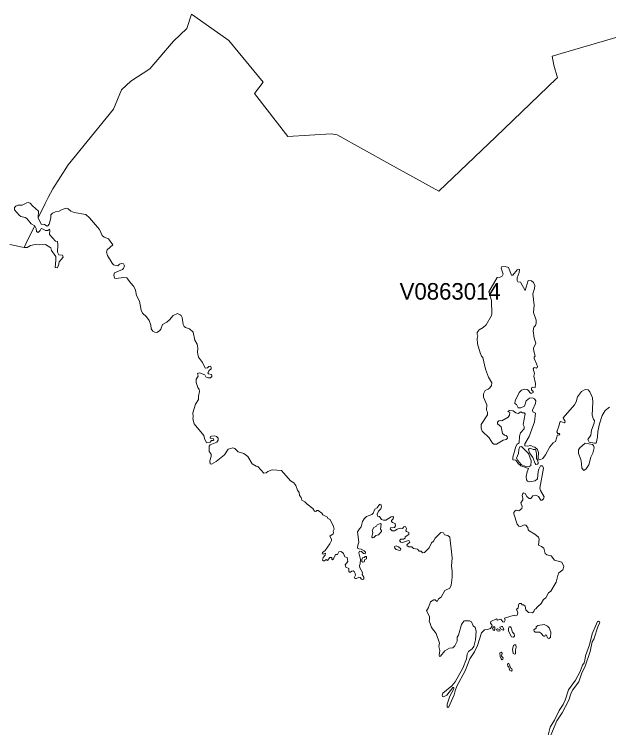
# Model space of a CAD drawing. Extents: x 369010 to 735936, y 6377141 to 6616555.
# Drawn here: x 477172 to 480757, y 6485532 to 6489836 of the extents above; entities that cross this region are included whole.
import ezdxf
from ezdxf.enums import TextEntityAlignment as Align

# ---------------------------------------------------------------- set-up
doc = ezdxf.new("R2010")
doc.units = 0
doc.header["$LTSCALE"] = 40
doc.layers.add('3', color=7, linetype='Continuous', lineweight=13)
doc.layers.add('4', color=7, linetype='Continuous')

msp = doc.modelspace()

# ---------------------------------------------------------------- linework, layer by layer
at = {"layer": '3'}
for points in [[(477144.89, 6488447.39), (477231.12, 6488427.7), (477252.3, 6488472.22), (477294.84, 6488559.6), (477273.16, 6488572.18), (477247.5, 6488604.29), (477237.74, 6488609.92), (477211.92, 6488614.72), (477200.67, 6488623.82), (477172.2, 6488655.1), (477172.86, 6488670.49), (477180.47, 6488678.27), (477193.71, 6488683.73), (477219.53, 6488683.07), (477247.5, 6488698.46), (477256.44, 6488700.45), (477268.36, 6488695.65), (477281.6, 6488679.59), (477318.5, 6488647.49), (477316.52, 6488608.43), (477357.73, 6488693.5), (477375.44, 6488730.57), (477404.9, 6488782.37), (477496.75, 6488927.68), (477770.83, 6489263.49), (477817.66, 6489379.51), (477873.94, 6489432.31), (477989.29, 6489506.95), (478131.96, 6489672.62), (478211.73, 6489749.41), (478240.03, 6489835.64), (478464.95, 6489676.42), (478672.99, 6489426.18), (478621.19, 6489358.49), (478821.94, 6489097.99), (479082.61, 6489114.37), (479118.2, 6489107.92), (479437.45, 6488931.32), (479732.05, 6488768.8), (480075.97, 6489096.33), (480441.07, 6489449.02), (480447.36, 6489452.5), (480425.51, 6489528.96), (480415.75, 6489582.91), (480423.86, 6489584.57), (480469.04, 6489599.3), (480862.61, 6489712.67)], [(480862.61, 6489712.67), (480469.04, 6489599.3), (480423.86, 6489584.57), (480415.75, 6489582.91), (480425.51, 6489528.96), (480447.36, 6489452.5), (480441.07, 6489449.02), (480075.97, 6489096.33), (479732.05, 6488768.8), (479437.45, 6488931.32), (479118.2, 6489107.92), (479082.61, 6489114.37), (478821.94, 6489097.99), (478621.19, 6489358.49), (478672.99, 6489426.18), (478464.95, 6489676.42), (478240.03, 6489835.64), (478211.73, 6489749.41), (478131.96, 6489672.62), (477989.29, 6489506.95), (477873.94, 6489432.31), (477817.66, 6489379.51), (477770.83, 6489263.49), (477496.75, 6488927.68), (477404.9, 6488782.37), (477375.44, 6488730.57), (477357.73, 6488693.5), (477316.52, 6488608.43), (477333.23, 6488568.71), (477354.09, 6488568.04), (477369.48, 6488558.28), (477374.28, 6488559.6), (477381.4, 6488569.37), (477393.15, 6488608.43), (477392.49, 6488625.14), (477402.91, 6488635.73), (477421.12, 6488644.67), (477442.63, 6488647.49), (477460.18, 6488657.25), (477484.51, 6488665.69), (477497.08, 6488662.88), (477513.14, 6488648.15), (477533.33, 6488639.21), (477603.01, 6488627.96), (477625.68, 6488608.59), (477685.59, 6488537.59), (477700.98, 6488500.52), (477714.22, 6488490.09), (477740.71, 6488480.33), (477766.52, 6488445.41), (477731.6, 6488414.79), (477728.79, 6488400.06), (477734.42, 6488381.36), (477761.56, 6488334.52), (477770.66, 6488324.09), (477797.14, 6488318.46), (477805.58, 6488327.57), (477818.16, 6488332.53), (477830.74, 6488330.38), (477836.86, 6488317.14), (477831.4, 6488301.75), (477823.62, 6488296.29), (477776.29, 6488275.27), (477772.15, 6488261.36), (477776.29, 6488243.99), (477785.39, 6488241.84), (477831.4, 6488248.12), (477851.59, 6488245.97), (477871.78, 6488216.02), (477891.98, 6488193.67), (477903.23, 6488170.67), (477908.03, 6488138.56), (477927.56, 6488105.79), (477936.66, 6488050.02), (477944.94, 6488033.3), (477968.77, 6488010.96), (477984.82, 6487988.61), (477995.25, 6487960.81), (477998.06, 6487937.8), (478007, 6487923.74), (478018.92, 6487917.45), (478032.16, 6487916.12), (478046.89, 6487925.23), (478055.16, 6487935.82), (478066.25, 6487964.78), (478091.24, 6487977.36), (478108.79, 6487991.92), (478130.47, 6488019.4), (478156.45, 6488029.66), (478171.68, 6488023.2), (478178.46, 6488018.57), (478184.59, 6488006.32), (478190.05, 6487964.78), (478195.84, 6487952.2), (478203.45, 6487945.75)], [(480048.99, 6488108.94), (480033.93, 6488160.41), (480083.91, 6488248.12), (480101.95, 6488249.28), (480114.86, 6488256.23), (480119.49, 6488267.98), (480107.25, 6488304.23), (480110.39, 6488311.51), (480132.9, 6488313.83), (480151.6, 6488308.04), (480170.64, 6488261.2), (480178.91, 6488261.53), (480203.9, 6488294.63), (480213.5, 6488298.44), (480218.8, 6488296.62), (480217.31, 6488277.09), (480204.4, 6488244.81), (480203.9, 6488228.76), (480208.54, 6488221.81), (480224.59, 6488220.32), (480252.39, 6488168.52), (480271.43, 6488228.76), (480291.95, 6488227.93), (480303.87, 6488217.34), (480310.32, 6488199.3), (480309.33, 6488181.76), (480299.89, 6488149.82), (480307.51, 6488080.8), (480302.71, 6488037.27), (480318.26, 6487989.94), (480318.76, 6487972.06), (480315.29, 6487958.33), (480305.36, 6487948.73), (480300.56, 6487926.72), (480308.17, 6487881.7), (480317.77, 6487851.58), (480303.87, 6487821.46), (480305.02, 6487804.24), (480314.13, 6487772.63), (480306.51, 6487766.51), (480307.34, 6487758.89), (480322.07, 6487727.28), (480326.37, 6487711.23), (480324.88, 6487703.95), (480318.6, 6487701.3), (480311.98, 6487705.44), (480304.36, 6487703.62), (480301.05, 6487697.16), (480309.82, 6487668.2), (480304.36, 6487652.48), (480315.78, 6487608.29), (480313.63, 6487584.62), (480299.07, 6487586.44), (480291.45, 6487582.3), (480291.12, 6487569.72), (480300.39, 6487559.46), (480300.39, 6487553.01), (480289.8, 6487546.88), (480281.03, 6487553.01), (480273.74, 6487566.74), (480264.97, 6487572.04), (480250.41, 6487573.53), (480231.38, 6487567.08), (480217.64, 6487554.17), (480191.65, 6487503.36), (480190.66, 6487487.3), (480201.25, 6487482.01), (480210.85, 6487461.81), (480227.24, 6487461.48), (480248.92, 6487471.41), (480258.02, 6487504.18), (480279.37, 6487520.24), (480298.07, 6487522.39), (480309.49, 6487515.27), (480316.78, 6487503.03), (480316.11, 6487487.8), (480296.25, 6487447.25), (480298.24, 6487437.82), (480315.12, 6487430.2), (480309, 6487376.75), (480276.06, 6487287.54), (480250.08, 6487243.68), (480250.41, 6487232.26), (480267.29, 6487229.94), (480286.32, 6487234.58), (480301.22, 6487226.14), (480311.81, 6487224.15), (480327.86, 6487209.26), (480332.83, 6487192.87), (480331.34, 6487158.28), (480333.99, 6487151.33), (480340.61, 6487146.86), (480359.31, 6487155.96), (480376.19, 6487176.98), (480402.34, 6487226.14), (480421.54, 6487249.31), (480435.28, 6487257.75), (480447.36, 6487297.8), (480456.13, 6487295.81), (480461.59, 6487300.45)], [(480236.17, 6486941.3), (480243.79, 6486947.76), (480253.72, 6486945.44), (480263.65, 6486926.41), (480276.39, 6486914.99), (480286.32, 6486914.99), (480299.73, 6486929.72), (480317.6, 6486935.51), (480332.83, 6486927.07), (480346.9, 6486904.56), (480354.51, 6486904.56), (480364.11, 6486913), (480367.92, 6486924.42), (480345.24, 6486962.16), (480341.44, 6486976.39), (480362.79, 6487097.21), (480356.99, 6487111.28), (480345.57, 6487110.95), (480334.48, 6487091.91), (480330.68, 6487077.02), (480327.7, 6487033.16), (480312.8, 6487021.24), (480280.03, 6487015.29), (480267.12, 6487019.42), (480260.67, 6487026.7), (480258.35, 6487047.56), (480263.98, 6487075.03), (480273.41, 6487094.89), (480227.24, 6487111.28), (480209.69, 6487126.17), (480197.12, 6487146.36), (480179.24, 6487146.86), (480177.59, 6487163.25), (480196.12, 6487228.45), (480204.89, 6487241.36), (480217.14, 6487250.96), (480218.63, 6487290.19), (480225.58, 6487310.38), (480246.6, 6487335.2), (480247.76, 6487348.11), (480240.15, 6487361.85), (480253.88, 6487425.57), (480247.43, 6487430.87), (480236.84, 6487430.87), (480226.91, 6487437.32), (480209.69, 6487427.39), (480197.12, 6487430.53), (480179.74, 6487443.11), (480158.06, 6487444.93), (480149.29, 6487438.98), (480160.37, 6487433.18), (480157.56, 6487416.47), (480150.44, 6487406.04), (480113.04, 6487382.54), (480102.78, 6487385.19), (480093.18, 6487383.2), (480087.06, 6487374.1), (480086.72, 6487365), (480108.24, 6487346.62), (480115.85, 6487306.9), (480128.76, 6487297.47), (480138.03, 6487294.82), (480144.15, 6487288.2), (480145.98, 6487278.44), (480139.19, 6487270.66), (480120.82, 6487266.52), (480080.1, 6487242.19), (480063.22, 6487241.36), (480055.94, 6487247.82), (480036.74, 6487279.43), (479993.71, 6487320.64), (479987.59, 6487338.18), (479987.92, 6487361.52), (480025.16, 6487419.11), (480025.16, 6487435.17), (480020.19, 6487446.59), (480022.51, 6487480.02), (480001.32, 6487526.69), (480001.66, 6487545.23), (480011.92, 6487565.09), (480030.29, 6487573.53), (480040.55, 6487581.97), (480049.32, 6487595.21), (480051.31, 6487611.27), (480032.77, 6487645.52), (480013.74, 6487694.84), (479996.69, 6487764.52), (479990.24, 6487772.63), (479981.8, 6487793.65), (479965.91, 6487846.61), (479963.09, 6487879.71), (479967.23, 6487896.1), (479963.42, 6487904.21), (479963.76, 6487915.63), (479976.33, 6487931.68), (479999.67, 6487946.08), (480017.05, 6487962.46), (480047.83, 6488013.94), (480051.97, 6488027.34), (480048.99, 6488108.94)], [(478203.45, 6487945.75), (478228.61, 6487937.31), (478250.46, 6487917.94), (478259.73, 6487868.62), (478274.29, 6487845.78), (478278.76, 6487820.96), (478277.27, 6487794.64), (478282.23, 6487766.51), (478306.4, 6487734.9), (478323.61, 6487701.3), (478337.68, 6487702.79), (478344.3, 6487710.9), (478352.57, 6487712.72), (478357.21, 6487710.9), (478359.86, 6487703.12), (478358.37, 6487696.67), (478346.45, 6487686.73), (478340, 6487672.01), (478342.31, 6487667.04), (478361.01, 6487662.74), (478363.99, 6487656.61), (478362.83, 6487649.83), (478354.89, 6487642.88), (478339.33, 6487641.72), (478327.75, 6487648.34), (478320.13, 6487660.42), (478288.52, 6487672.01), (478277.43, 6487668.53), (478281.24, 6487652.14), (478268.99, 6487634.6), (478268.17, 6487615.07), (478278.43, 6487583.13), (478287.53, 6487571.21), (478289.85, 6487560.12), (478281.9, 6487531.66), (478282.07, 6487511.8), (478264.86, 6487483.99), (478248.14, 6487431.36), (478251.12, 6487408.03), (478249.3, 6487395.12), (478256.75, 6487365.33), (478314.34, 6487295.15), (478318.15, 6487276.12), (478331.22, 6487250.14), (478352.57, 6487255.1), (478361.35, 6487264.2), (478371.28, 6487263.87), (478374.75, 6487267.68), (478371.77, 6487275.62), (478352.24, 6487278.44), (478354.89, 6487288.2), (478361.01, 6487291.01), (478380.87, 6487292.84), (478391.14, 6487287.87), (478401.73, 6487277.61), (478401.4, 6487266.19), (478393.12, 6487253.94), (478353.4, 6487238.72), (478346.45, 6487230.27), (478346.45, 6487198.66), (478359.86, 6487181.12), (478359.86, 6487168.54), (478350.75, 6487141.07), (478352.57, 6487124.35), (478361.01, 6487121.54), (478389.15, 6487137.59), (478439.63, 6487178.8), (478461.64, 6487212.07), (478490.77, 6487220.34), (478501.2, 6487215.38), (478522.88, 6487195.52), (478555.81, 6487185.26), (478580.64, 6487168.54), (478606.95, 6487123.52), (478629.79, 6487110.12), (478640.88, 6487107.14), (478677.13, 6487067.42), (478691.53, 6487068.91), (478700.96, 6487077.02), (478726.78, 6487086.62), (478782.72, 6487083.47), (478838.33, 6487020.91), (478858.19, 6487009.49), (478869.28, 6486992.78), (478879.54, 6486964.81), (478888.97, 6486951.57), (478892.78, 6486933.2), (478901.05, 6486921.44), (478905.69, 6486905.06), (478925.05, 6486894.63), (478937.3, 6486880.9), (478972.55, 6486853.59), (478981.82, 6486838.69), (478990.59, 6486835.55), (478995.89, 6486841.67), (479004.99, 6486842), (479026.01, 6486826.11), (479033.62, 6486815.69), (479060.27, 6486802.78), (479063.41, 6486793.68)], [(480461.59, 6487300.45), (480458.61, 6487305.74), (480450.67, 6487307.4), (480444.54, 6487317.33), (480458.61, 6487356.22), (480461.43, 6487375.92), (480467.55, 6487378.24), (480488.24, 6487371.45), (480493.53, 6487375.92), (480492.37, 6487385.52), (480484.43, 6487394.62), (480482.94, 6487401.57), (480549.97, 6487479.36), (480560.89, 6487498.39), (480568.01, 6487528.18), (480592.5, 6487558.97), (480614.19, 6487571.21), (480632.89, 6487570.55), (480643.48, 6487557.48), (480658.87, 6487520.9), (480661.02, 6487495.74), (480657.55, 6487416.8), (480664.66, 6487391.97), (480671.28, 6487385.19), (480669.3, 6487367.97), (480652.91, 6487326.43), (480648.28, 6487296.64), (480631.56, 6487270.66), (480638.02, 6487254.77), (480671.62, 6487247.49), (480680.72, 6487248.98), (480688.83, 6487284.89), (480690.32, 6487318.82), (480700.41, 6487364.17), (480717.96, 6487415.97), (480735.83, 6487445.43), (480761.15, 6487465.95)], [(479903.02, 6485975.59), (479898.38, 6485946.96), (479877.53, 6485891.68), (479830.69, 6485808.93), (479810.83, 6485783.44), (479757.21, 6485741.07), (479751.91, 6485728.82), (479754.56, 6485719.72), (479761.01, 6485718.56), (479779.71, 6485728.82), (479816.46, 6485773.84), (479823.24, 6485773.84), (479822.41, 6485766.23), (479798.09, 6485721.21), (479782.86, 6485673.21), (479782.03, 6485658.32), (479785.84, 6485654.51), (479792.29, 6485657.99), (479824.57, 6485729.65), (479830.36, 6485754.48), (479841.28, 6485781.45), (479890.44, 6485875.79), (479919.4, 6485946.63), (479946.38, 6485989.33), (479966.4, 6486027.89), (479989.9, 6486103.85), (480007.45, 6486122.39), (480024.99, 6486124.38), (480042.87, 6486130.83), (480053.13, 6486145.73), (480051.64, 6486152.18), (480042.87, 6486162.44), (480045.51, 6486171.71), (480080.1, 6486187.6), (480085.4, 6486180.48), (480107.08, 6486186.94), (480119, 6486171.21), (480126.28, 6486169.39), (480132.73, 6486179.99), (480127.77, 6486192.56), (480186.19, 6486210.94), (480194.96, 6486207.13), (480204.89, 6486211.27), (480208.04, 6486223.85), (480201.09, 6486247.18), (480211.02, 6486253.64), (480212.18, 6486270.02), (480217.14, 6486280.28), (480228.56, 6486280.78), (480234.69, 6486273.5), (480243.13, 6486272.67), (480252.56, 6486265.06), (480257.52, 6486242.88), (480272.75, 6486227.32), (480297.58, 6486224.67), (480305.52, 6486233.44), (480308.33, 6486245.69), (480316.28, 6486248.34), (480324.88, 6486259.43), (480349.71, 6486280.28), (480364.11, 6486305.11), (480377.02, 6486315.87), (480394.23, 6486345.49), (480407.47, 6486356.25), (480439.74, 6486408.88), (480449.34, 6486449.59), (480456.63, 6486465.98), (480480.62, 6486484.68), (480486.75, 6486503.88), (480474, 6486529.7), (480430.81, 6486543.1), (480410.28, 6486569.09), (480383.64, 6486574.38), (480373.21, 6486581.66), (480364.77, 6486614.43), (480352.03, 6486625.85), (480332.99, 6486633.8), (480336.8, 6486670.04), (480333.82, 6486680.8), (480310.49, 6486699.83), (480277.88, 6486718.54), (480271.76, 6486726.15), (480268.78, 6486738.73), (480256.2, 6486752.8), (480245.94, 6486754.78), (480226.41, 6486746.34), (480215.49, 6486748.33), (480204.4, 6486760.08), (480184.37, 6486821.81), (480184.7, 6486830.58), (480190.5, 6486839.02), (480198.77, 6486843.66), (480215.16, 6486840.51), (480233.2, 6486853.92), (480233.86, 6486866.17), (480226.24, 6486889.01), (480238.16, 6486906.88), (480239.32, 6486917.14), (480233.86, 6486930.22), (480236.17, 6486941.3)], [(479063.41, 6486793.68), (479076.32, 6486787.22), (479097.84, 6486745.51), (479100.49, 6486729.13), (479094.03, 6486718.21), (479096.68, 6486709.43), (479094.36, 6486701.66), (479074.17, 6486687.26), (479084.1, 6486668.89), (479084.27, 6486660.61), (479075.16, 6486640.25), (479046.53, 6486600.37), (479030.48, 6486589.61), (479028.99, 6486580.51), (479034.28, 6486578.52), (479048.02, 6486583.82), (479046.2, 6486572.07), (479034.78, 6486558.33), (479031.64, 6486543.43), (479036.27, 6486539.3), (479043.06, 6486539.3), (479052.16, 6486545.75), (479060.93, 6486540.79), (479074.17, 6486558), (479087.58, 6486559.16), (479086.09, 6486548.73), (479090.56, 6486544.92), (479096.68, 6486550.72), (479109.59, 6486575.87), (479121.17, 6486576.7), (479129.95, 6486591.93), (479140.54, 6486594.24), (479151.96, 6486589.28), (479158.08, 6486581.66), (479164.87, 6486563.29), (479180.26, 6486559.49), (479183.24, 6486534.99), (479167.68, 6486514.14), (479171.65, 6486500.4), (479189.86, 6486491.3), (479188.7, 6486474.75), (479193.33, 6486469.45), (479199.13, 6486469.12), (479207.9, 6486476.74), (479215.02, 6486477.89), (479221.64, 6486474.42), (479228.42, 6486461.18), (479228.75, 6486451.25), (479222.3, 6486435.52), (479228.75, 6486431.39), (479234.88, 6486431.72), (479250.1, 6486440.49), (479257.72, 6486438.67), (479266.16, 6486428.74), (479273.77, 6486425.93), (479279.56, 6486429.9), (479280.72, 6486440.16), (479270.46, 6486455.05), (479271.95, 6486468.29), (479255.89, 6486495.44), (479253.58, 6486510.99), (479258.38, 6486519.44), (479259.2, 6486547.24), (479250.76, 6486587.29), (479254.24, 6486596.89), (479266.82, 6486594.57), (479277.74, 6486583.15), (479288.5, 6486580.84), (479290.32, 6486591.1), (479282.71, 6486599.21), (479263.01, 6486608.31), (479250.76, 6486609.8), (479242.32, 6486615.59), (479243.15, 6486631.98), (479250.6, 6486650.68), (479241.83, 6486712.41), (479252.92, 6486732.27), (479263.18, 6486743.36), (479271.29, 6486775.3), (479281.55, 6486791.03), (479296.44, 6486806.25), (479327.72, 6486817.34), (479336.5, 6486826.45), (479346.43, 6486849.78), (479359.83, 6486858.06), (479374.23, 6486878.74), (479382.34, 6486879.41), (479386.81, 6486864.51), (479381.84, 6486851.93), (479367.78, 6486837.04), (479360.33, 6486820.32), (479362.98, 6486808.07), (479373.73, 6486806.58), (479386.31, 6486787.88), (479398.72, 6486782.92), (479412.79, 6486782.92), (479444.9, 6486803.11), (479455.16, 6486805.1), (479458.97, 6486801.62), (479456.32, 6486792.19)], [(479456.32, 6486792.19), (479446.72, 6486781.76), (479446.72, 6486774.97), (479452.84, 6486769.18), (479468.9, 6486762.73), (479470.88, 6486750.48), (479464.43, 6486740.22), (479455, 6486736.74), (479443.58, 6486738.73), (479438.94, 6486730.78), (479450.03, 6486719.7), (479464.43, 6486720.03), (479480.15, 6486729.63), (479498.36, 6486734.92), (479513.25, 6486733.43), (479521.69, 6486743.69), (479530.8, 6486745.18), (479536.59, 6486733.43), (479533.94, 6486720.36), (479536.92, 6486714.73), (479550.66, 6486708.94), (479552.15, 6486696.69), (479529.64, 6486684.11), (479528.98, 6486674.35), (479519.05, 6486669.71), (479502.66, 6486668.89), (479496.87, 6486663.59), (479496.87, 6486657.47), (479502.16, 6486651.01), (479512.59, 6486648.03), (479548.34, 6486660.94), (479554.13, 6486658.29), (479556.45, 6486651.34), (479538.91, 6486635.29), (479541.55, 6486628.17), (479550.49, 6486623.54), (479570.35, 6486622.38), (479579.79, 6486612.45), (479604.28, 6486608.97), (479613.05, 6486597.55), (479626.29, 6486596.89), (479632.75, 6486586.96), (479646.48, 6486588.78), (479673.79, 6486616.26), (479687.53, 6486646.87), (479699.78, 6486657.13), (479710.37, 6486675.34), (479744.79, 6486710.1), (479759.52, 6486707.45), (479766.31, 6486695.7), (479785.67, 6486691.89), (479798.25, 6486681.46), (479812.15, 6486556.01), (479809.17, 6486506.03), (479813.31, 6486475.25), (479812.98, 6486439), (479806.2, 6486391.67), (479799.08, 6486373.79), (479768.96, 6486358.57), (479746.78, 6486318.51), (479729.73, 6486310.07), (479724.27, 6486296), (479718.15, 6486295.51), (479710.2, 6486303.95), (479701.1, 6486302.79), (479682.07, 6486290.21), (479669.99, 6486257.11), (479657.74, 6486236.42), (479675.78, 6486203.32), (479676.94, 6486184.95), (479673.46, 6486173.86), (479680.41, 6486160.62), (479687.03, 6486135.47), (479716.66, 6486099.55), (479737.01, 6486041.63), (479731.72, 6486022.1), (479738.17, 6485998.43), (479733.7, 6485970.29), (479737.01, 6485960.69), (479741.65, 6485962.68), (479769.12, 6485994.62), (479796.6, 6486010.68), (479817.62, 6486013.82), (479829.7, 6486025.57), (479842.11, 6486053.87), (479842.44, 6486077.04), (479851.71, 6486090.45), (479868.09, 6486153.34), (479882.16, 6486174.36), (479887.46, 6486177.34), (479917.58, 6486175.52), (479929, 6486169.73), (479940.09, 6486147.22), (479951.51, 6486135.47), (479957.63, 6486114.45), (479952.67, 6486061.49), (479942.9, 6486022.1), (479932.64, 6486008.03), (479911.79, 6485990.82), (479903.02, 6485975.59)], [(480396.71, 6485461.86), (480444.54, 6485573.58), (480476.32, 6485622.07), (480516.87, 6485697.21), (480527.96, 6485735.77), (480539.05, 6485757.79), (480577.28, 6485807.77), (480592.17, 6485856.59), (480615.51, 6485902.44), (480644.97, 6485990.82), (480657.38, 6486049.9), (480667.64, 6486065.62), (480692.8, 6486145.73), (480702.73, 6486163.6), (480701.24, 6486170.88), (480695.45, 6486174.69), (480688.99, 6486172.04), (480682.21, 6486158.97), (480657.55, 6486097.57), (480641.16, 6486031.69), (480615.84, 6485965), (480613.19, 6485939.84), (480607.9, 6485923.29), (480597.8, 6485909.22), (480584.06, 6485870), (480555.76, 6485818.86), (480514.06, 6485760.1), (480495.02, 6485698.37), (480482.44, 6485671.72), (480458.94, 6485636.14), (480429.98, 6485577.88), (480403.83, 6485535.51), (480388.27, 6485469.97)]]:
    msp.add_lwpolyline(points, dxfattribs=at)
for points in [[(477294.84, 6488559.6), (477252.3, 6488472.22), (477231.12, 6488427.7), (477248.83, 6488429.19), (477269.68, 6488440.44), (477297.65, 6488447.39), (477324.79, 6488443.92), (477360.38, 6488445.9), (477391.82, 6488426.37), (477395.3, 6488410.32), (477422.44, 6488373.41), (477423.1, 6488353.22), (477417.64, 6488307.87), (477430.05, 6488305.06), (477439.16, 6488320.45), (477442.63, 6488342.79), (477465.64, 6488369.94), (477462.16, 6488383.18), (477441.31, 6488385.33), (477431.54, 6488401.38), (477433.7, 6488445.9), (477431.54, 6488464.11), (477420.29, 6488466.09), (477383.38, 6488507.3), (477386.86, 6488532.46), (477384.04, 6488539.41), (477373.62, 6488531.8), (477359.72, 6488530.97), (477345.81, 6488540.07), (477334.56, 6488542.89), (477328.27, 6488531.8), (477315.03, 6488519.22), (477306.75, 6488524.85), (477303.94, 6488542.89)], [(480275.07, 6487105.15), (480286.49, 6487113.93), (480289.63, 6487141.9), (480272.75, 6487184.93), (480230.38, 6487228.45), (480221.28, 6487226.14), (480214.82, 6487210.41), (480212.51, 6487185.75), (480200.26, 6487158.61), (480208.04, 6487143.39), (480229.72, 6487120.05), (480254.05, 6487107.97)], [(480615.34, 6487248.65), (480581.91, 6487219.68), (480573.97, 6487207.77), (480574.3, 6487185.26), (480588.86, 6487149.51), (480593.33, 6487124.68), (480594.16, 6487096.88), (480606.08, 6487082.65), (480621.63, 6487092.58), (480636.53, 6487117.73), (480648.45, 6487163.58), (480661.85, 6487187.24), (480668.8, 6487219.68), (480665.99, 6487234.08), (480658.04, 6487241.03)], [(480318.1, 6487120.05), (480326.54, 6487120.88), (480331.17, 6487126.5), (480328.53, 6487143.72), (480321.24, 6487155.14), (480321.91, 6487188.73), (480314.79, 6487209.75), (480300.22, 6487209.75), (480283.51, 6487218.52), (480277.72, 6487217.03), (480273.58, 6487210.41), (480279.21, 6487189.89), (480299.89, 6487161.26), (480312.47, 6487125.51)], [(479379.86, 6486763.88), (479360.82, 6486755.11), (479356.52, 6486747.83), (479340.14, 6486739.06), (479329.87, 6486721.18), (479334.84, 6486709.76), (479328.39, 6486681.46), (479332.85, 6486678.15), (479340.14, 6486679.31), (479351.56, 6486691.89), (479369.1, 6486695.2), (479387.47, 6486715.39), (479386.64, 6486722.34), (479380.52, 6486728.47), (479384.33, 6486760.41)], [(479496.04, 6486600.37), (479501.83, 6486602.52), (479503.82, 6486610.63), (479489.59, 6486623.21), (479475.19, 6486628.17), (479464.1, 6486623.87), (479466.42, 6486613.94), (479474.36, 6486606.32)], [(479295.78, 6486564.45), (479288.83, 6486564.78), (479283.53, 6486558.66), (479272.11, 6486557.17), (479267.48, 6486547.24), (479267.48, 6486534.33), (479274.43, 6486530.19), (479282.04, 6486532.84), (479286.51, 6486545.75), (479296.94, 6486551.05)], [(480396.22, 6486069.76), (480405.65, 6486075.22), (480406.81, 6486107.5), (480397.21, 6486133.98), (480388.11, 6486144.57), (480367.92, 6486153.67), (480329.35, 6486147.55), (480319.92, 6486141.09), (480318.76, 6486133.15), (480306.18, 6486121.73), (480307.67, 6486113.62), (480313.8, 6486107.5), (480340.11, 6486107.16), (480351.2, 6486100.38), (480359.97, 6486086.97), (480366.1, 6486083.17), (480371.39, 6486084.66), (480375.86, 6486092.27), (480381.65, 6486089.62), (480386.95, 6486073.57)], [(480065.54, 6486119.08), (480070.84, 6486124.38), (480069.02, 6486139.6), (480061.73, 6486141.09), (480055.28, 6486129.34), (480059.09, 6486121.4)], [(480092.35, 6486114.78), (480101.79, 6486115.61), (480097.65, 6486123.22), (480085.4, 6486129.01), (480080.1, 6486124.38), (480083.08, 6486116.76)], [(480120.49, 6486119.41), (480123.96, 6486124.05), (480115.52, 6486141.59), (480109.4, 6486142.75), (480100.63, 6486137.29), (480103.77, 6486127.85)], [(480181.56, 6486077.87), (480188.68, 6486083.17), (480186.85, 6486098.06), (480177.26, 6486107.66), (480168.48, 6486134.97), (480163.52, 6486139.93), (480157.39, 6486139.93), (480151.44, 6486130), (480153.26, 6486114.45), (480170.8, 6486080.19)], [(480189.83, 6485974.93), (480194.47, 6485978.24), (480194.8, 6486001.57), (480198.61, 6486017.63), (480197.61, 6486031.36), (480187.68, 6486031.69), (480181.89, 6486027.06), (480175.77, 6486005.38), (480181.06, 6485979.89)], [(480112.87, 6485941.99), (480119, 6485944.31), (480119.83, 6485953.58), (480109.9, 6485963.84), (480114.36, 6485980.89), (480107.25, 6485988.17), (480100.63, 6485984.36), (480101.45, 6485962.18), (480107.58, 6485946.63)], [(480169.97, 6485873.47), (480174.44, 6485879.1), (480173.28, 6485886.38), (480166.5, 6485891.68), (480155.08, 6485919.15), (480149.29, 6485919.48), (480146.64, 6485914.68), (480147.8, 6485903.1), (480153.92, 6485896.64), (480161.2, 6485877.61)]]:
    msp.add_lwpolyline(points, close=True, dxfattribs=at)

# ---------------------------------------------------------------- texts
at = {"layer": '4'}
msp.add_text('V0863014', height=100, dxfattribs=at).set_placement((479800.78, 6488114.05), align=Align.CENTER)

doc.saveas('drawing.dxf')
